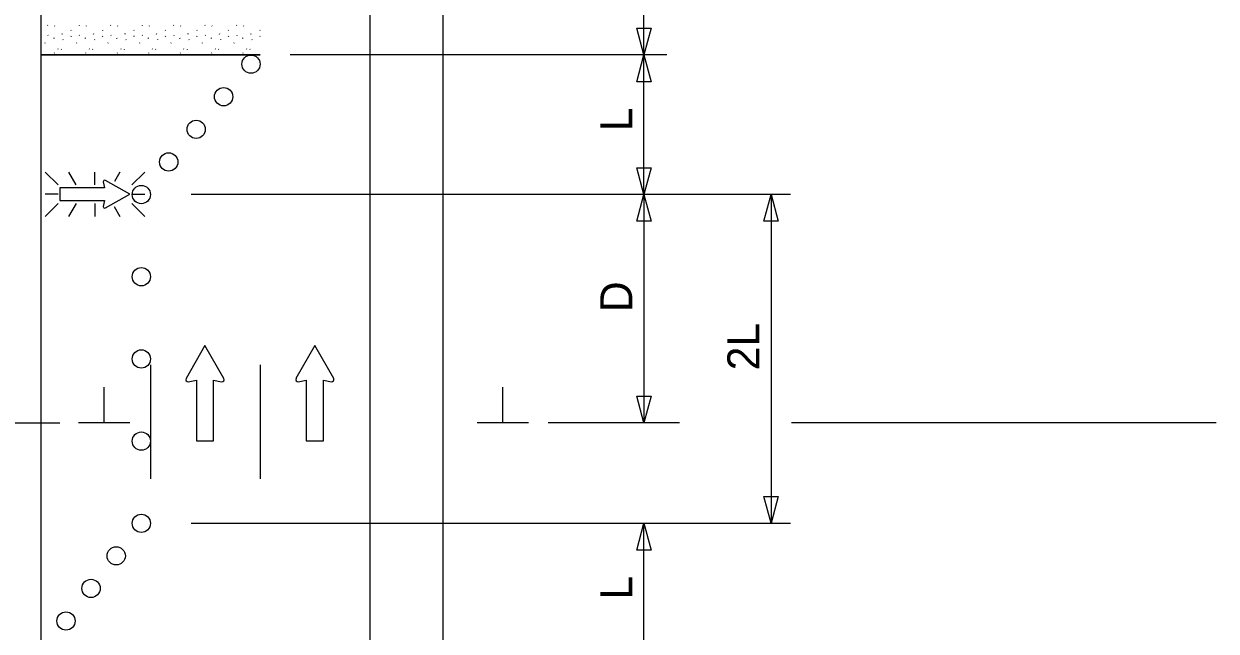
# Model space of a CAD drawing. Extents: x 16590 to 19508, y 5703 to 6974.
# Drawn here: x 17913.2 to 18174.2, y 6562.3 to 6695.4 of the extents above; entities that cross this region are included whole.
import ezdxf

# ---------------------------------------------------------------- set-up
doc = ezdxf.new("R2010")
doc.units = 0
for name, color, linetype in [('ALI_LEGAL_EX', 7, 'Continuous'), ('MT_SCRATCH_LEVEL_A', 7, 'Continuous'), ('MT_SCRATCH_LEVEL_E', 7, 'Continuous'), ('PAVT_EDGE_EX', 7, 'Continuous'), ('TRAFFIC_SIGNS_PR', 7, 'Continuous'), ('TYPICAL_TEXT_DIMEN_PR', 7, 'Continuous')]:
    doc.layers.add(name, color=color, linetype=linetype)

msp = doc.modelspace()

# ---------------------------------------------------------------- linework, layer by layer
at = {"layer": 'ALI_LEGAL_EX'}
for points in [[(17940.96, 6620.69), (17940.96, 6595.69)], [(17964.96, 6620.69), (17964.96, 6595.69)]]:
    msp.add_lwpolyline(points, dxfattribs=at)
at = {"layer": 'MT_SCRATCH_LEVEL_A'}
msp.add_line((17964.96, 6688.54), (17916.96, 6688.54), dxfattribs=at)
at = {"layer": 'MT_SCRATCH_LEVEL_E'}
for p, q in [((17952.86, 6624.9), (17948.75, 6617.66)), ((17957.01, 6617.66), (17952.86, 6624.9)), ((17976.91, 6624.9), (17972.8, 6617.66)), ((17981.06, 6617.66), (17976.91, 6624.9)), ((17949.23, 6616.98), (17951.01, 6617.29)), ((17951.01, 6617.29), (17951.01, 6604.03)), ((17954.75, 6604.03), (17954.75, 6617.29)), ((17954.75, 6617.29), (17956.53, 6616.98)), ((17973.28, 6616.98), (17975.06, 6617.29)), ((17975.06, 6617.29), (17975.06, 6604.03)), ((17978.8, 6604.03), (17978.8, 6617.29)), ((17978.8, 6617.29), (17980.58, 6616.98)), ((17951.01, 6604.03), (17954.75, 6604.03)), ((17975.06, 6604.03), (17978.8, 6604.03))]:
    msp.add_line(p, q, dxfattribs=at)
for centre, start, end in [((17949.16, 6617.43), 150.4248, 279.9638), ((17956.6, 6617.43), 260.0362, 29.7731), ((17973.21, 6617.43), 150.4248, 279.9638), ((17980.65, 6617.43), 260.0362, 29.7731)]:
    msp.add_arc(centre, 0.463, start, end, dxfattribs=at)
at = {"layer": 'PAVT_EDGE_EX'}
for p, q in [((17916.96, 6925.33), (17916.96, 6243.41)), ((17988.96, 6925.33), (17988.96, 6243.41)), ((18004.96, 6925.33), (18004.96, 6243.41)), ((17916.96, 6717.96), (17916.96, 6688.54)), ((17918.45, 6695.06), (17918.51, 6694.98)), ((17918.5, 6692.85), (17918.55, 6692.77)), ((17919.98, 6694.92), (17920.04, 6694.84)), ((17921.63, 6693.13), (17921.68, 6693.25)), ((17923.55, 6694), (17923.6, 6693.92)), ((17923.59, 6692.6), (17923.65, 6692.72)), ((17925.34, 6695.06), (17925.39, 6694.98)), ((17925.39, 6692.85), (17925.44, 6692.77)), ((17926.87, 6694.92), (17926.92, 6694.84)), ((17928.51, 6693.13), (17928.56, 6693.25)), ((17930.44, 6694), (17930.49, 6693.92)), ((17930.48, 6692.6), (17930.53, 6692.72)), ((17932.23, 6695.06), (17932.28, 6694.98)), ((17932.28, 6692.85), (17932.33, 6692.77)), ((17933.76, 6694.92), (17933.81, 6694.84)), ((17935.4, 6693.13), (17935.45, 6693.25)), ((17937.33, 6694), (17937.38, 6693.92)), ((17937.37, 6692.6), (17937.42, 6692.72)), ((17939.12, 6695.06), (17939.17, 6694.98)), ((17939.17, 6692.85), (17939.22, 6692.77)), ((17940.65, 6694.92), (17940.7, 6694.84)), ((17942.29, 6693.13), (17942.34, 6693.25)), ((17944.21, 6694), (17944.26, 6693.92)), ((17944.26, 6692.6), (17944.31, 6692.72)), ((17946, 6695.06), (17946.06, 6694.98)), ((17946.05, 6692.85), (17946.1, 6692.77)), ((17947.53, 6694.92), (17947.59, 6694.84)), ((17949.18, 6693.13), (17949.23, 6693.25)), ((17951.1, 6694), (17951.15, 6693.92)), ((17951.14, 6692.6), (17951.19, 6692.72)), ((17952.89, 6695.06), (17952.94, 6694.98)), ((17952.94, 6692.85), (17952.99, 6692.77)), ((17954.42, 6694.92), (17954.47, 6694.84)), ((17956.06, 6693.13), (17956.12, 6693.25)), ((17957.99, 6694), (17958.04, 6693.92)), ((17958.03, 6692.6), (17958.08, 6692.72)), ((17959.78, 6695.06), (17959.83, 6694.98)), ((17959.83, 6692.85), (17959.88, 6692.77)), ((17961.31, 6694.92), (17961.36, 6694.84)), ((17962.95, 6693.13), (17963, 6693.25)), ((17964.88, 6694), (17964.93, 6693.92)), ((17964.92, 6692.6), (17964.96, 6692.69)), ((17917.88, 6691.1), (17917.94, 6691.21)), ((17919.78, 6692.27), (17919.8, 6692.16)), ((17921.81, 6691.93), (17921.87, 6691.85)), ((17924.77, 6691.1), (17924.82, 6691.21)), ((17926.67, 6692.27), (17926.69, 6692.16)), ((17928.7, 6691.93), (17928.75, 6691.85)), ((17931.66, 6691.1), (17931.71, 6691.21)), ((17933.56, 6692.27), (17933.57, 6692.16)), ((17935.59, 6691.93), (17935.64, 6691.85)), ((17938.55, 6691.1), (17938.6, 6691.21)), ((17940.45, 6692.27), (17940.46, 6692.16)), ((17942.48, 6691.93), (17942.53, 6691.85)), ((17945.43, 6691.1), (17945.49, 6691.21)), ((17947.33, 6692.27), (17947.35, 6692.16)), ((17949.36, 6691.93), (17949.42, 6691.85)), ((17952.32, 6691.1), (17952.37, 6691.21)), ((17954.22, 6692.27), (17954.24, 6692.16)), ((17956.25, 6691.93), (17956.3, 6691.85)), ((17959.21, 6691.1), (17959.26, 6691.21)), ((17961.11, 6692.27), (17961.12, 6692.16)), ((17963.14, 6691.93), (17963.19, 6691.85)), ((17916.96, 6688.54), (17964.96, 6688.54)), ((17919.9, 6688.9), (17919.96, 6689.02)), ((17920.67, 6689.86), (17920.72, 6689.78)), ((17921.4, 6689.83), (17921.46, 6689.75)), ((17923.72, 6688.6), (17923.78, 6688.72)), ((17926.79, 6688.9), (17926.84, 6689.02)), ((17927.56, 6689.86), (17927.61, 6689.78)), ((17928.29, 6689.83), (17928.35, 6689.75)), ((17930.61, 6688.6), (17930.66, 6688.72)), ((17933.68, 6688.9), (17933.73, 6689.02)), ((17934.44, 6689.86), (17934.49, 6689.78)), ((17935.18, 6689.83), (17935.23, 6689.75)), ((17937.5, 6688.6), (17937.55, 6688.72)), ((17940.57, 6688.9), (17940.62, 6689.02)), ((17941.33, 6689.86), (17941.38, 6689.78)), ((17942.07, 6689.83), (17942.12, 6689.75)), ((17944.39, 6688.6), (17944.44, 6688.72)), ((17947.45, 6688.9), (17947.51, 6689.02)), ((17948.22, 6689.86), (17948.27, 6689.78)), ((17948.96, 6689.83), (17949.01, 6689.75)), ((17951.27, 6688.6), (17951.33, 6688.72)), ((17954.34, 6688.9), (17954.39, 6689.02)), ((17955.11, 6689.86), (17955.16, 6689.78)), ((17955.84, 6689.83), (17955.9, 6689.75)), ((17958.16, 6688.6), (17958.21, 6688.72)), ((17961.23, 6688.9), (17961.28, 6689.02)), ((17961.99, 6689.86), (17962.05, 6689.78)), ((17962.73, 6689.83), (17962.78, 6689.75))]:
    msp.add_line(p, q, dxfattribs=at)
at = {"layer": 'TRAFFIC_SIGNS_PR'}
for p, q in [((17920.73, 6660.07), (17917.91, 6662.9)), ((17923.03, 6662.9), (17924.66, 6660.07)), ((17928.82, 6660.07), (17928.82, 6662.9)), ((17934.29, 6662.9), (17933.08, 6660.8)), ((17939.72, 6662.89), (17936.9, 6660.07)), ((17920.73, 6658.04), (17917.91, 6658.04)), ((17936.9, 6658.04), (17939.72, 6658.04)), ((17920.73, 6656.01), (17917.91, 6653.19)), ((17924.68, 6656.01), (17923.05, 6653.19)), ((17928.82, 6656.01), (17928.82, 6653.19)), ((17933, 6655.38), (17934.26, 6653.19)), ((17939.72, 6653.19), (17936.9, 6656.01))]:
    msp.add_line(p, q, dxfattribs=at)
for points in [[(17930.64, 6660.73), (17930.87, 6659.43), (17921.15, 6659.43), (17921.15, 6656.69), (17930.87, 6656.69), (17930.64, 6655.38)], [(17931.14, 6655.03), (17936.45, 6658.04), (17931.14, 6661.08)]]:
    msp.add_lwpolyline(points, dxfattribs=at)
for centre in [(17962.96, 6686.53), (17956.96, 6679.39), (17950.96, 6672.25), (17944.96, 6665.11), (17938.96, 6657.97), (17938.96, 6639.97), (17938.96, 6621.97), (17938.96, 6603.97), (17938.96, 6585.97), (17933.46, 6578.84), (17927.96, 6571.71), (17922.47, 6564.58)]:
    msp.add_circle(centre, 2, dxfattribs=at)
for centre, start, end in [((17930.98, 6660.78), 61.4833, 189.9593), ((17930.98, 6655.33), 170.7308, 298.8916)]:
    msp.add_arc(centre, 0.341, start, end, dxfattribs=at)
at = {"layer": 'TYPICAL_TEXT_DIMEN_PR'}
for p, q in [((18048.96, 6688.54), (18048.96, 6717.96)), ((18048.96, 6688.54), (18047.39, 6694.4)), ((18047.39, 6694.4), (18048.96, 6694.4)), ((18048.96, 6694.4), (18050.53, 6694.4)), ((18050.53, 6694.4), (18048.96, 6688.54)), ((18053.96, 6688.54), (17971.56, 6688.54)), ((18047.39, 6682.67), (18048.96, 6688.54)), ((18048.96, 6657.97), (18048.96, 6688.54)), ((18048.96, 6688.54), (18050.53, 6682.67)), ((18048.96, 6682.67), (18047.39, 6682.67)), ((18050.53, 6682.67), (18048.96, 6682.67)), ((18048.96, 6657.97), (18047.39, 6663.83)), ((18047.39, 6663.83), (18048.96, 6663.83)), ((18048.96, 6663.83), (18050.53, 6663.83)), ((18050.53, 6663.83), (18048.96, 6657.97)), ((18081, 6657.97), (17949.86, 6657.97)), ((18047.39, 6652.11), (18048.96, 6657.97)), ((18048.96, 6657.97), (18048.96, 6607.97)), ((18048.96, 6657.97), (18050.53, 6652.11)), ((18075.19, 6652.11), (18076.76, 6657.97)), ((18076.76, 6657.97), (18078.33, 6652.11)), ((18076.76, 6657.97), (18076.76, 6585.97)), ((18048.96, 6652.11), (18047.39, 6652.11)), ((18050.53, 6652.11), (18048.96, 6652.11)), ((18076.76, 6652.11), (18075.19, 6652.11)), ((18078.33, 6652.11), (18076.76, 6652.11)), ((17930.81, 6607.97), (17930.81, 6615.76)), ((18018.08, 6607.97), (18018.08, 6615.76)), ((18048.96, 6607.97), (18047.39, 6613.83)), ((18047.39, 6613.83), (18048.96, 6613.83)), ((18048.96, 6613.83), (18050.53, 6613.83)), ((18050.53, 6613.83), (18048.96, 6607.97)), ((18076.76, 6612.84), (18076.76, 6609.07)), ((17815.96, 6607.97), (17921.15, 6607.97)), ((17936.43, 6607.97), (17925.18, 6607.97)), ((18023.71, 6607.97), (18012.46, 6607.97)), ((18056.71, 6607.97), (18027.96, 6607.97)), ((18174.17, 6607.97), (18081.25, 6607.97)), ((18076.76, 6585.97), (18075.19, 6591.83)), ((18075.19, 6591.83), (18076.76, 6591.83)), ((18076.76, 6591.83), (18078.33, 6591.83)), ((18078.33, 6591.83), (18076.76, 6585.97)), ((17949.86, 6585.97), (18081, 6585.97)), ((18047.39, 6580.11), (18048.96, 6585.97)), ((18048.96, 6555.41), (18048.96, 6585.97)), ((18048.96, 6585.97), (18050.53, 6580.11)), ((18048.96, 6580.11), (18047.39, 6580.11)), ((18050.53, 6580.11), (18048.96, 6580.11))]:
    msp.add_line(p, q, dxfattribs=at)

# ---------------------------------------------------------------- texts
for s, p in [('L', (18046.4, 6671.83)), ('D', (18046.4, 6632.19)), ('2L', (18074.21, 6619.47)), ('L', (18046.4, 6569.26))]:
    msp.add_text(s, height=7, rotation=90, dxfattribs=at).set_placement(p)

doc.saveas('drawing.dxf')
